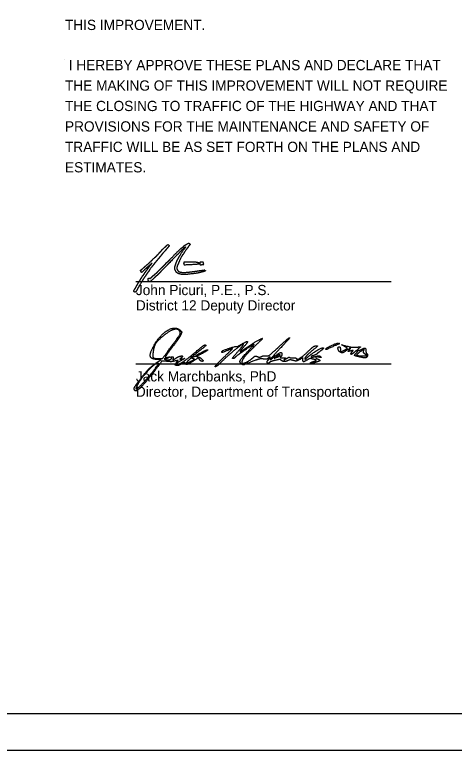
# Model space of a CAD drawing. Extents: x -10.1 to 68, y -9.5 to 29.2.
# Drawn here: x 23.84 to 29.86, y 0 to 10.07 of the extents above; entities that cross this region are included whole.
import ezdxf

# ---------------------------------------------------------------- set-up
doc = ezdxf.new("R2010")
doc.units = 0
for name, color, linetype in [('SH_Border', 7, 'Continuous'), ('SH_Cut_Line', 7, 'Continuous'), ('SH_Data', 7, 'Continuous'), ('SH_Text', 7, 'Continuous')]:
    doc.layers.add(name, color=color, linetype=linetype)

msp = doc.modelspace()

# ---------------------------------------------------------------- linework, layer by layer
at = {"layer": 'SH_Border'}
msp.add_lwpolyline([(1.5, 21.5), (33.5, 21.5), (33.5, 0.5), (1.5, 0.5)], close=True, dxfattribs=at)
at = {"layer": 'SH_Cut_Line'}
msp.add_lwpolyline([(0, 0), (34, 0), (34, 22), (0, 22)], close=True, dxfattribs=at)
at = {"layer": 'SH_Data'}
for p, q in [((24.528, 9.455), (24.528, 9.455)), ((25.5, 6.421), (29, 6.421)), ((25.5, 5.292), (29, 5.292))]:
    msp.add_line(p, q, dxfattribs=at)
at = {"layer": 'SH_Text'}
for p, q in [((26.156, 6.66), (26.156, 6.66)), ((26.379, 6.653), (26.379, 6.653)), ((25.675, 6.428), (25.675, 6.428)), ((25.484, 6.276), (25.484, 6.276)), ((25.962, 5.497), (25.962, 5.497)), ((28.102, 5.496), (28.102, 5.496)), ((26.283, 5.365), (26.283, 5.365)), ((26.328, 5.407), (26.328, 5.407)), ((26.699, 5.378), (26.699, 5.378)), ((27.477, 5.409), (27.477, 5.409)), ((28.554, 5.39), (28.554, 5.39))]:
    msp.add_line(p, q, dxfattribs=at)
for points in [[(25.925, 6.917), (25.936, 6.927), (25.945, 6.922)], [(25.719, 6.669), (25.722, 6.676), (25.716, 6.669)], [(26.249, 6.684), (26.158, 6.685), (26.156, 6.677)], [(26.401, 6.685), (26.379, 6.685), (26.376, 6.672)], [(26.415, 6.655), (26.429, 6.655), (26.428, 6.668)], [(28.365, 5.486), (28.402, 5.508), (28.361, 5.531)], [(25.815, 5.33), (25.845, 5.351), (25.807, 5.352)], [(26.058, 5.31), (26.079, 5.342), (26.037, 5.332)], [(27.425, 5.389), (27.395, 5.364), (27.436, 5.383)], [(28.614, 5.403), (28.67, 5.403), (28.642, 5.425)]]:
    msp.add_lwpolyline(points, dxfattribs=at)
for points in [[(25.853, 6.847), (25.853, 6.848), (25.866, 6.862), (25.883, 6.878)], [(25.91, 6.853), (25.899, 6.841), (25.868, 6.806), (25.857, 6.793)], [(25.883, 6.878), (25.9, 6.893), (25.919, 6.911), (25.925, 6.917)], [(25.928, 6.874), (25.921, 6.866), (25.913, 6.856), (25.91, 6.853)], [(25.948, 6.898), (25.944, 6.894), (25.935, 6.883), (25.928, 6.874)], [(25.945, 6.922), (25.957, 6.915), (25.957, 6.909), (25.948, 6.898)], [(25.971, 6.726), (26.041, 6.8), (26.133, 6.888), (26.142, 6.89)], [(26.091, 6.755), (26.103, 6.778), (26.158, 6.862), (26.165, 6.868)], [(26.134, 6.856), (26.125, 6.848), (26.118, 6.841), (26.118, 6.84)], [(26.182, 6.893), (26.182, 6.895), (26.157, 6.876), (26.134, 6.856)], [(26.142, 6.89), (26.146, 6.892), (26.15, 6.894), (26.15, 6.896)], [(26.15, 6.896), (26.15, 6.902), (26.176, 6.921), (26.202, 6.935)], [(26.165, 6.868), (26.169, 6.872), (26.182, 6.891), (26.182, 6.893)], [(26.21, 6.884), (26.202, 6.875), (26.199, 6.87), (26.172, 6.831)], [(26.202, 6.935), (26.225, 6.947), (26.23, 6.947), (26.24, 6.935)], [(26.214, 6.891), (26.214, 6.889), (26.212, 6.886), (26.21, 6.884)], [(26.224, 6.904), (26.219, 6.898), (26.214, 6.892), (26.214, 6.891)], [(26.233, 6.916), (26.233, 6.915), (26.229, 6.909), (26.224, 6.904)], [(26.239, 6.924), (26.236, 6.921), (26.233, 6.917), (26.233, 6.916)], [(26.24, 6.935), (26.243, 6.931), (26.243, 6.929), (26.239, 6.924)], [(25.743, 6.734), (25.759, 6.75), (25.776, 6.764), (25.779, 6.766)], [(25.779, 6.766), (25.783, 6.767), (25.785, 6.768), (25.784, 6.769)], [(25.784, 6.769), (25.783, 6.77), (25.786, 6.774), (25.79, 6.778)], [(25.79, 6.778), (25.794, 6.782), (25.797, 6.786), (25.796, 6.787)], [(25.796, 6.787), (25.795, 6.788), (25.797, 6.79), (25.801, 6.791)], [(25.801, 6.791), (25.805, 6.792), (25.808, 6.794), (25.808, 6.796)], [(25.808, 6.796), (25.808, 6.797), (25.818, 6.809), (25.83, 6.821)], [(25.835, 6.765), (25.829, 6.758), (25.818, 6.744), (25.809, 6.733)], [(25.83, 6.821), (25.842, 6.834), (25.853, 6.846), (25.853, 6.847)], [(25.857, 6.793), (25.851, 6.785), (25.841, 6.772), (25.835, 6.765)], [(26.066, 6.786), (26.064, 6.786), (26.034, 6.755), (25.964, 6.682)], [(26.102, 6.825), (26.102, 6.823), (26.069, 6.786), (26.066, 6.786)], [(26.076, 6.729), (26.078, 6.731), (26.085, 6.743), (26.091, 6.755)], [(26.144, 6.789), (26.137, 6.783), (26.097, 6.707), (26.085, 6.676)], [(26.106, 6.828), (26.104, 6.828), (26.102, 6.827), (26.102, 6.825)], [(26.118, 6.84), (26.118, 6.836), (26.11, 6.828), (26.106, 6.828)], [(26.172, 6.831), (26.158, 6.809), (26.145, 6.79), (26.144, 6.789)], [(25.65, 6.648), (25.668, 6.662), (25.702, 6.694), (25.743, 6.734)], [(25.716, 6.669), (25.704, 6.657), (25.681, 6.637), (25.657, 6.617)], [(25.691, 6.635), (25.694, 6.64), (25.701, 6.648), (25.706, 6.653)], [(25.706, 6.653), (25.711, 6.659), (25.717, 6.666), (25.719, 6.669)], [(25.743, 6.653), (25.734, 6.642), (25.726, 6.631), (25.724, 6.629)], [(25.76, 6.674), (25.759, 6.673), (25.751, 6.664), (25.743, 6.653)], [(25.774, 6.692), (25.767, 6.683), (25.761, 6.675), (25.76, 6.674)], [(25.79, 6.711), (25.788, 6.709), (25.781, 6.701), (25.774, 6.692)], [(25.809, 6.733), (25.801, 6.723), (25.792, 6.713), (25.79, 6.711)], [(25.869, 6.625), (25.879, 6.635), (25.892, 6.648), (25.898, 6.653)], [(25.964, 6.682), (25.939, 6.656), (25.903, 6.619), (25.885, 6.601)], [(25.898, 6.653), (25.905, 6.659), (25.91, 6.664), (25.91, 6.666)], [(25.91, 6.666), (25.91, 6.668), (25.919, 6.677), (25.93, 6.687)], [(25.93, 6.687), (25.941, 6.697), (25.959, 6.714), (25.971, 6.726)], [(26.038, 6.633), (26.04, 6.637), (26.043, 6.649), (26.046, 6.658)], [(26.046, 6.658), (26.051, 6.675), (26.07, 6.718), (26.076, 6.729)], [(26.076, 6.657), (26.064, 6.629), (26.06, 6.593), (26.069, 6.579)], [(26.085, 6.676), (26.082, 6.669), (26.078, 6.66), (26.076, 6.657)], [(26.156, 6.677), (26.154, 6.672), (26.155, 6.665), (26.156, 6.66)], [(26.156, 6.66), (26.16, 6.65), (26.163, 6.65), (26.256, 6.655)], [(26.343, 6.681), (26.341, 6.683), (26.299, 6.684), (26.249, 6.684)], [(26.256, 6.655), (26.357, 6.66), (26.394, 6.668), (26.361, 6.676)], [(26.361, 6.676), (26.353, 6.678), (26.345, 6.68), (26.343, 6.681)], [(26.376, 6.672), (26.374, 6.66), (26.374, 6.657), (26.379, 6.653)], [(26.379, 6.653), (26.386, 6.648), (26.4, 6.647), (26.4, 6.652)], [(26.4, 6.652), (26.4, 6.654), (26.406, 6.655), (26.415, 6.655)], [(26.424, 6.683), (26.423, 6.684), (26.413, 6.685), (26.401, 6.685)], [(26.428, 6.668), (26.427, 6.675), (26.425, 6.682), (26.424, 6.683)], [(25.569, 6.559), (25.563, 6.571), (25.563, 6.577), (25.57, 6.58)], [(25.615, 6.578), (25.584, 6.547), (25.577, 6.544), (25.569, 6.559)], [(25.57, 6.58), (25.574, 6.581), (25.586, 6.59), (25.597, 6.601)], [(25.597, 6.601), (25.619, 6.622), (25.624, 6.627), (25.65, 6.648)], [(25.657, 6.617), (25.644, 6.605), (25.625, 6.588), (25.615, 6.578)], [(25.617, 6.53), (25.621, 6.538), (25.629, 6.549), (25.633, 6.553)], [(25.633, 6.553), (25.637, 6.558), (25.641, 6.564), (25.642, 6.567)], [(25.642, 6.567), (25.643, 6.57), (25.646, 6.572), (25.648, 6.572)], [(25.648, 6.572), (25.649, 6.572), (25.651, 6.574), (25.651, 6.577)], [(25.651, 6.577), (25.651, 6.579), (25.652, 6.581), (25.654, 6.581)], [(25.654, 6.581), (25.656, 6.581), (25.657, 6.583), (25.657, 6.586)], [(25.657, 6.586), (25.657, 6.589), (25.659, 6.592), (25.661, 6.595)], [(25.677, 6.563), (25.677, 6.561), (25.673, 6.556), (25.658, 6.538)], [(25.661, 6.595), (25.673, 6.607), (25.683, 6.623), (25.681, 6.627)], [(25.724, 6.629), (25.717, 6.622), (25.677, 6.566), (25.677, 6.563)], [(25.681, 6.627), (25.68, 6.629), (25.68, 6.63), (25.682, 6.628)], [(25.682, 6.628), (25.684, 6.627), (25.688, 6.63), (25.691, 6.635)], [(25.785, 6.541), (25.797, 6.553), (25.843, 6.598), (25.869, 6.625)], [(25.885, 6.601), (25.866, 6.582), (25.838, 6.553), (25.821, 6.536)], [(26.04, 6.575), (26.034, 6.587), (26.033, 6.622), (26.038, 6.633)], [(26.102, 6.523), (26.076, 6.53), (26.049, 6.553), (26.04, 6.575)], [(26.069, 6.579), (26.082, 6.559), (26.095, 6.552), (26.128, 6.546)], [(26.128, 6.546), (26.149, 6.543), (26.16, 6.543), (26.216, 6.549)], [(26.216, 6.549), (26.272, 6.555), (26.322, 6.562), (26.353, 6.567)], [(26.4, 6.549), (26.362, 6.539), (26.323, 6.532), (26.229, 6.521)], [(26.353, 6.567), (26.366, 6.569), (26.396, 6.573), (26.406, 6.574)], [(26.431, 6.556), (26.427, 6.556), (26.413, 6.553), (26.4, 6.549)], [(26.406, 6.574), (26.411, 6.574), (26.414, 6.575), (26.414, 6.575)], [(26.414, 6.575), (26.414, 6.575), (26.421, 6.576), (26.43, 6.577)], [(26.43, 6.577), (26.442, 6.578), (26.444, 6.577), (26.438, 6.575)], [(26.438, 6.575), (26.431, 6.573), (26.431, 6.572), (26.442, 6.572)], [(26.443, 6.561), (26.44, 6.558), (26.435, 6.556), (26.431, 6.556)], [(26.442, 6.572), (26.449, 6.572), (26.454, 6.57), (26.454, 6.569)], [(26.451, 6.565), (26.449, 6.565), (26.445, 6.563), (26.443, 6.561)], [(26.454, 6.569), (26.454, 6.567), (26.453, 6.565), (26.451, 6.565)], [(25.548, 6.425), (25.565, 6.454), (25.573, 6.466), (25.58, 6.477)], [(25.58, 6.477), (25.585, 6.484), (25.59, 6.493), (25.593, 6.497)], [(25.616, 6.476), (25.602, 6.454), (25.589, 6.434), (25.587, 6.432)], [(25.593, 6.497), (25.595, 6.501), (25.598, 6.505), (25.6, 6.505)], [(25.6, 6.505), (25.602, 6.505), (25.603, 6.507), (25.603, 6.509)], [(25.603, 6.509), (25.603, 6.512), (25.604, 6.514), (25.606, 6.514)], [(25.606, 6.514), (25.607, 6.514), (25.612, 6.521), (25.617, 6.53)], [(25.645, 6.517), (25.644, 6.517), (25.631, 6.498), (25.616, 6.476)], [(25.651, 6.527), (25.649, 6.523), (25.646, 6.518), (25.645, 6.517)], [(25.658, 6.538), (25.656, 6.536), (25.653, 6.531), (25.651, 6.527)], [(25.67, 6.447), (25.67, 6.465), (25.672, 6.467), (25.686, 6.465)], [(25.749, 6.468), (25.702, 6.422), (25.687, 6.414), (25.675, 6.428)], [(25.686, 6.465), (25.697, 6.463), (25.699, 6.465), (25.717, 6.481)], [(25.717, 6.481), (25.727, 6.491), (25.744, 6.506), (25.755, 6.515)], [(25.782, 6.498), (25.777, 6.494), (25.762, 6.48), (25.749, 6.468)], [(25.755, 6.515), (25.765, 6.524), (25.779, 6.536), (25.785, 6.541)], [(25.821, 6.536), (25.805, 6.519), (25.787, 6.502), (25.782, 6.498)], [(26.229, 6.521), (26.188, 6.516), (26.122, 6.517), (26.102, 6.523)], [(25.484, 6.315), (25.492, 6.327), (25.503, 6.345), (25.508, 6.356)], [(25.508, 6.356), (25.513, 6.366), (25.519, 6.376), (25.52, 6.376)], [(25.52, 6.376), (25.522, 6.377), (25.523, 6.379), (25.523, 6.381)], [(25.523, 6.381), (25.523, 6.383), (25.528, 6.392), (25.533, 6.401)], [(25.533, 6.401), (25.539, 6.41), (25.546, 6.421), (25.548, 6.425)], [(25.543, 6.357), (25.539, 6.35), (25.536, 6.344), (25.536, 6.343)], [(25.559, 6.384), (25.555, 6.375), (25.547, 6.363), (25.543, 6.357)], [(25.587, 6.432), (25.585, 6.429), (25.581, 6.422), (25.559, 6.384)], [(25.675, 6.428), (25.671, 6.432), (25.669, 6.439), (25.67, 6.447)], [(25.474, 6.285), (25.469, 6.292), (25.47, 6.294), (25.484, 6.315)], [(25.484, 6.276), (25.481, 6.277), (25.477, 6.281), (25.474, 6.285)], [(25.491, 6.275), (25.49, 6.275), (25.487, 6.276), (25.484, 6.276)], [(25.517, 6.311), (25.517, 6.307), (25.493, 6.274), (25.491, 6.275)], [(25.526, 6.328), (25.521, 6.32), (25.517, 6.312), (25.517, 6.311)], [(25.536, 6.343), (25.536, 6.342), (25.531, 6.335), (25.526, 6.328)], [(25.751, 5.548), (25.837, 5.698), (26.045, 5.814), (26.111, 5.748)], [(26.102, 5.739), (26.076, 5.781), (25.95, 5.74), (25.855, 5.658)], [(26.111, 5.748), (26.13, 5.73), (26.13, 5.724), (26.112, 5.686)], [(25.855, 5.658), (25.788, 5.601), (25.749, 5.537), (25.738, 5.466)], [(25.962, 5.497), (26.084, 5.66), (26.116, 5.716), (26.102, 5.739)], [(26.112, 5.686), (26.101, 5.663), (26.049, 5.588), (25.997, 5.518)], [(27.459, 5.526), (27.534, 5.596), (27.6, 5.652), (27.606, 5.652)], [(27.606, 5.652), (27.611, 5.652), (27.559, 5.592), (27.49, 5.519)], [(25.807, 5.352), (25.71, 5.353), (25.686, 5.435), (25.751, 5.548)], [(26.341, 5.474), (26.392, 5.517), (26.437, 5.552), (26.442, 5.552)], [(26.442, 5.552), (26.467, 5.553), (26.444, 5.527), (26.358, 5.46)], [(26.974, 5.559), (26.964, 5.569), (26.754, 5.402), (26.677, 5.323)], [(27.114, 5.559), (27.065, 5.531), (26.877, 5.399), (26.863, 5.383)], [(26.88, 5.53), (26.886, 5.528), (26.915, 5.542), (26.946, 5.56)], [(26.896, 5.459), (26.942, 5.511), (26.977, 5.556), (26.974, 5.559)], [(26.946, 5.56), (27.025, 5.606), (27.037, 5.592), (26.978, 5.525)], [(27.14, 5.545), (27.041, 5.451), (26.952, 5.343), (26.952, 5.316)], [(27.005, 5.506), (27.085, 5.563), (27.217, 5.64), (27.232, 5.64)], [(27.049, 5.48), (27.095, 5.529), (27.124, 5.565), (27.114, 5.559)], [(27.232, 5.64), (27.237, 5.64), (27.196, 5.597), (27.14, 5.545)], [(28.102, 5.496), (28.102, 5.508), (28.254, 5.579), (28.273, 5.575)], [(28.273, 5.575), (28.294, 5.571), (28.295, 5.571), (28.173, 5.517)], [(28.361, 5.531), (28.318, 5.555), (28.317, 5.555), (28.42, 5.529)], [(25.738, 5.466), (25.727, 5.393), (25.748, 5.365), (25.816, 5.365)], [(25.816, 5.365), (25.863, 5.365), (25.867, 5.369), (25.962, 5.497)], [(25.997, 5.518), (25.944, 5.449), (25.902, 5.388), (25.902, 5.383)], [(26.08, 5.29), (26.103, 5.29), (26.229, 5.379), (26.341, 5.474)], [(26.358, 5.46), (26.265, 5.387), (26.243, 5.365), (26.287, 5.389)], [(26.328, 5.407), (26.348, 5.425), (26.48, 5.491), (26.485, 5.485)], [(26.485, 5.485), (26.491, 5.479), (26.349, 5.402), (26.331, 5.402)], [(26.677, 5.462), (26.677, 5.472), (26.864, 5.535), (26.88, 5.53)], [(26.758, 5.477), (26.695, 5.451), (26.676, 5.447), (26.677, 5.462)], [(26.699, 5.378), (26.77, 5.446), (26.826, 5.502), (26.822, 5.502)], [(26.822, 5.502), (26.819, 5.502), (26.79, 5.491), (26.758, 5.477)], [(26.83, 5.365), (26.82, 5.365), (26.849, 5.406), (26.896, 5.459)], [(26.942, 5.294), (26.917, 5.319), (26.946, 5.37), (27.049, 5.48)], [(26.978, 5.525), (26.95, 5.493), (26.927, 5.464), (26.927, 5.459)], [(26.927, 5.459), (26.927, 5.455), (26.962, 5.476), (27.005, 5.506)], [(27.284, 5.404), (27.317, 5.401), (27.341, 5.418), (27.459, 5.526)], [(27.49, 5.519), (27.361, 5.381), (27.329, 5.334), (27.411, 5.401)], [(27.411, 5.401), (27.459, 5.441), (27.502, 5.452), (27.502, 5.424)], [(27.702, 5.363), (27.702, 5.341), (27.797, 5.402), (27.867, 5.47)], [(27.939, 5.492), (27.865, 5.431), (27.814, 5.378), (27.814, 5.361)], [(27.848, 5.379), (27.902, 5.428), (28.049, 5.518), (28.066, 5.512)], [(27.867, 5.47), (27.912, 5.514), (27.95, 5.54), (27.967, 5.539)], [(27.967, 5.539), (27.992, 5.539), (27.988, 5.532), (27.939, 5.492)], [(28.032, 5.47), (28.005, 5.45), (27.98, 5.43), (27.977, 5.426)], [(28.066, 5.512), (28.074, 5.509), (28.059, 5.491), (28.032, 5.47)], [(28.173, 5.517), (28.111, 5.489), (28.102, 5.486), (28.102, 5.496)], [(28.303, 5.452), (28.276, 5.466), (28.265, 5.527), (28.289, 5.527)], [(28.289, 5.527), (28.296, 5.527), (28.302, 5.513), (28.302, 5.496)], [(28.302, 5.496), (28.302, 5.459), (28.316, 5.457), (28.365, 5.486)], [(28.377, 5.47), (28.337, 5.444), (28.324, 5.44), (28.303, 5.452)], [(28.425, 5.482), (28.449, 5.511), (28.434, 5.507), (28.377, 5.47)], [(28.444, 5.47), (28.411, 5.462), (28.409, 5.463), (28.425, 5.482)], [(28.42, 5.529), (28.441, 5.523), (28.486, 5.521), (28.52, 5.522)], [(28.464, 5.459), (28.479, 5.477), (28.477, 5.478), (28.444, 5.47)], [(28.493, 5.45), (28.461, 5.42), (28.438, 5.427), (28.464, 5.459)], [(28.518, 5.438), (28.549, 5.471), (28.527, 5.482), (28.493, 5.45)], [(28.52, 5.522), (28.575, 5.526), (28.58, 5.524), (28.56, 5.509)], [(28.561, 5.448), (28.518, 5.417), (28.535, 5.403), (28.614, 5.403)], [(28.56, 5.509), (28.531, 5.488), (28.554, 5.471), (28.588, 5.489)], [(28.622, 5.471), (28.632, 5.496), (28.624, 5.493), (28.561, 5.448)], [(28.588, 5.489), (28.628, 5.511), (28.652, 5.505), (28.652, 5.474)], [(28.642, 5.425), (28.621, 5.441), (28.615, 5.454), (28.622, 5.471)], [(28.652, 5.474), (28.652, 5.458), (28.658, 5.438), (28.666, 5.431)], [(25.908, 5.364), (25.885, 5.363), (25.886, 5.362), (25.912, 5.352)], [(25.902, 5.383), (25.902, 5.379), (25.917, 5.378), (25.936, 5.383)], [(25.952, 5.378), (25.941, 5.371), (25.922, 5.365), (25.908, 5.364)], [(25.912, 5.352), (25.942, 5.34), (25.998, 5.364), (25.981, 5.382)], [(25.936, 5.383), (25.961, 5.389), (25.965, 5.387), (25.952, 5.378)], [(25.981, 5.382), (25.976, 5.386), (25.982, 5.39), (25.995, 5.39)], [(25.995, 5.39), (26.009, 5.39), (26.014, 5.383), (26.01, 5.371)], [(26.01, 5.371), (26.001, 5.348), (26.013, 5.347), (26.046, 5.369)], [(26.046, 5.369), (26.075, 5.389), (26.139, 5.407), (26.139, 5.395)], [(26.124, 5.341), (26.073, 5.312), (26.053, 5.29), (26.08, 5.29)], [(26.117, 5.371), (26.099, 5.357), (26.101, 5.355), (26.133, 5.36)], [(26.139, 5.395), (26.139, 5.39), (26.129, 5.379), (26.117, 5.371)], [(26.133, 5.36), (26.17, 5.366), (26.17, 5.366), (26.124, 5.341)], [(26.23, 5.349), (26.185, 5.308), (26.197, 5.299), (26.255, 5.329)], [(26.283, 5.365), (26.266, 5.372), (26.249, 5.366), (26.23, 5.349)], [(26.255, 5.329), (26.301, 5.353), (26.305, 5.357), (26.283, 5.365)], [(26.287, 5.389), (26.3, 5.396), (26.324, 5.398), (26.34, 5.393)], [(26.373, 5.352), (26.356, 5.376), (26.354, 5.376), (26.289, 5.333)], [(26.331, 5.402), (26.326, 5.402), (26.325, 5.404), (26.328, 5.407)], [(26.34, 5.393), (26.376, 5.384), (26.435, 5.327), (26.408, 5.327)], [(26.408, 5.327), (26.398, 5.327), (26.383, 5.338), (26.373, 5.352)], [(26.589, 5.253), (26.579, 5.253), (26.628, 5.309), (26.699, 5.378)], [(26.863, 5.383), (26.855, 5.373), (26.84, 5.365), (26.83, 5.365)], [(27.141, 5.342), (26.995, 5.284), (26.96, 5.276), (26.942, 5.294)], [(26.97, 5.302), (26.991, 5.302), (27.073, 5.348), (27.109, 5.38)], [(27.109, 5.38), (27.129, 5.398), (27.142, 5.401), (27.166, 5.392)], [(27.247, 5.359), (27.218, 5.363), (27.178, 5.356), (27.141, 5.342)], [(27.166, 5.392), (27.186, 5.384), (27.205, 5.385), (27.221, 5.394)], [(27.221, 5.394), (27.234, 5.401), (27.263, 5.406), (27.284, 5.404)], [(27.317, 5.373), (27.301, 5.359), (27.28, 5.355), (27.247, 5.359)], [(27.313, 5.302), (27.295, 5.302), (27.3, 5.335), (27.32, 5.352)], [(27.339, 5.381), (27.339, 5.388), (27.329, 5.385), (27.317, 5.373)], [(27.32, 5.352), (27.331, 5.361), (27.339, 5.374), (27.339, 5.381)], [(27.408, 5.34), (27.369, 5.331), (27.335, 5.318), (27.332, 5.313)], [(27.492, 5.342), (27.481, 5.353), (27.461, 5.353), (27.408, 5.34)], [(27.477, 5.409), (27.477, 5.422), (27.452, 5.413), (27.425, 5.389)], [(27.436, 5.383), (27.458, 5.394), (27.477, 5.406), (27.477, 5.409)], [(27.487, 5.392), (27.475, 5.381), (27.481, 5.377), (27.513, 5.377)], [(27.502, 5.424), (27.502, 5.415), (27.495, 5.401), (27.487, 5.392)], [(27.588, 5.339), (27.558, 5.323), (27.51, 5.324), (27.492, 5.342)], [(27.513, 5.377), (27.551, 5.377), (27.553, 5.375), (27.537, 5.356)], [(27.537, 5.356), (27.525, 5.341), (27.532, 5.343), (27.559, 5.362)], [(27.559, 5.362), (27.581, 5.377), (27.601, 5.386), (27.605, 5.382)], [(27.653, 5.34), (27.626, 5.347), (27.603, 5.347), (27.588, 5.339)], [(27.605, 5.382), (27.609, 5.378), (27.632, 5.375), (27.657, 5.375)], [(27.742, 5.351), (27.704, 5.332), (27.686, 5.33), (27.653, 5.34)], [(27.657, 5.375), (27.682, 5.375), (27.702, 5.37), (27.702, 5.363)], [(27.789, 5.351), (27.789, 5.374), (27.788, 5.374), (27.742, 5.351)], [(27.851, 5.348), (27.806, 5.321), (27.789, 5.322), (27.789, 5.351)], [(27.814, 5.361), (27.814, 5.354), (27.83, 5.362), (27.848, 5.379)], [(27.934, 5.356), (27.895, 5.366), (27.879, 5.364), (27.851, 5.348)], [(27.942, 5.409), (27.893, 5.394), (27.912, 5.38), (27.964, 5.394)], [(27.964, 5.337), (27.975, 5.341), (27.964, 5.348), (27.934, 5.356)], [(27.977, 5.426), (27.973, 5.422), (27.958, 5.414), (27.942, 5.409)], [(27.964, 5.394), (28.002, 5.404), (28.018, 5.404), (28.03, 5.392)], [(28.011, 5.384), (27.974, 5.393), (27.961, 5.37), (27.995, 5.357)], [(27.995, 5.357), (28.026, 5.345), (28.017, 5.33), (27.97, 5.315)], [(28.03, 5.392), (28.042, 5.379), (28.039, 5.377), (28.011, 5.384)], [(28.554, 5.39), (28.499, 5.403), (28.494, 5.41), (28.518, 5.438)], [(28.672, 5.397), (28.664, 5.376), (28.623, 5.373), (28.554, 5.39)], [(28.666, 5.431), (28.674, 5.423), (28.677, 5.408), (28.672, 5.397)], [(25.808, 5.301), (25.787, 5.322), (25.568, 5.096), (25.522, 5.005)], [(25.564, 5.088), (25.641, 5.188), (25.721, 5.265), (25.815, 5.33)], [(25.592, 5.024), (25.659, 5.093), (25.815, 5.293), (25.808, 5.301)], [(25.896, 5.33), (25.862, 5.333), (25.851, 5.323), (25.774, 5.221)], [(26.037, 5.332), (25.997, 5.323), (25.974, 5.322), (25.896, 5.33)], [(26.056, 5.27), (26.038, 5.277), (26.038, 5.281), (26.058, 5.31)], [(26.123, 5.29), (26.097, 5.275), (26.067, 5.266), (26.056, 5.27)], [(26.174, 5.304), (26.171, 5.312), (26.152, 5.307), (26.123, 5.29)], [(26.289, 5.333), (26.22, 5.289), (26.182, 5.279), (26.174, 5.304)], [(26.677, 5.323), (26.639, 5.284), (26.599, 5.253), (26.589, 5.253)], [(26.952, 5.316), (26.952, 5.309), (26.96, 5.302), (26.97, 5.302)], [(27.332, 5.313), (27.328, 5.307), (27.32, 5.302), (27.313, 5.302)], [(27.97, 5.315), (27.924, 5.299), (27.876, 5.305), (27.92, 5.321)], [(27.92, 5.321), (27.934, 5.326), (27.954, 5.333), (27.964, 5.337)], [(25.774, 5.221), (25.622, 5.019), (25.477, 4.89), (25.477, 4.957)], [(25.477, 4.957), (25.477, 4.967), (25.516, 5.026), (25.564, 5.088)], [(25.522, 5.005), (25.491, 4.945), (25.522, 4.953), (25.592, 5.024)]]:
    msp.add_open_spline(points, degree=2, dxfattribs=at)

# ---------------------------------------------------------------- texts
at = {"layer": 'SH_Data'}
for s, p in [(' I HEREBY APPROVE THESE PLANS AND DECLARE THAT', (24.528, 9.315)), ('THE MAKING OF THIS IMPROVEMENT WILL NOT REQUIRE', (24.528, 9.035)), ('THE CLOSING TO TRAFFIC OF THE HIGHWAY AND THAT', (24.528, 8.755)), ('PROVISIONS FOR THE MAINTENANCE AND SAFETY OF', (24.528, 8.475)), ('TRAFFIC WILL BE AS SET FORTH ON THE PLANS AND', (24.528, 8.195)), ('ESTIMATES.', (24.528, 7.915))]:
    msp.add_text(s, height=0.14, dxfattribs=at).set_placement(p)
at = {"layer": 'SH_Text'}
for s, p in [('THIS IMPROVEMENT.', (24.528, 9.865)), ('John Picuri, P.E., P.S.', (25.5, 6.234)), ('District 12 Deputy Director', (25.5, 6.024)), ('Jack Marchbanks, PhD', (25.5, 5.052)), ('Director, Department of Transportation', (25.5, 4.842))]:
    msp.add_text(s, height=0.14, dxfattribs=at).set_placement(p)

doc.saveas('drawing.dxf')
